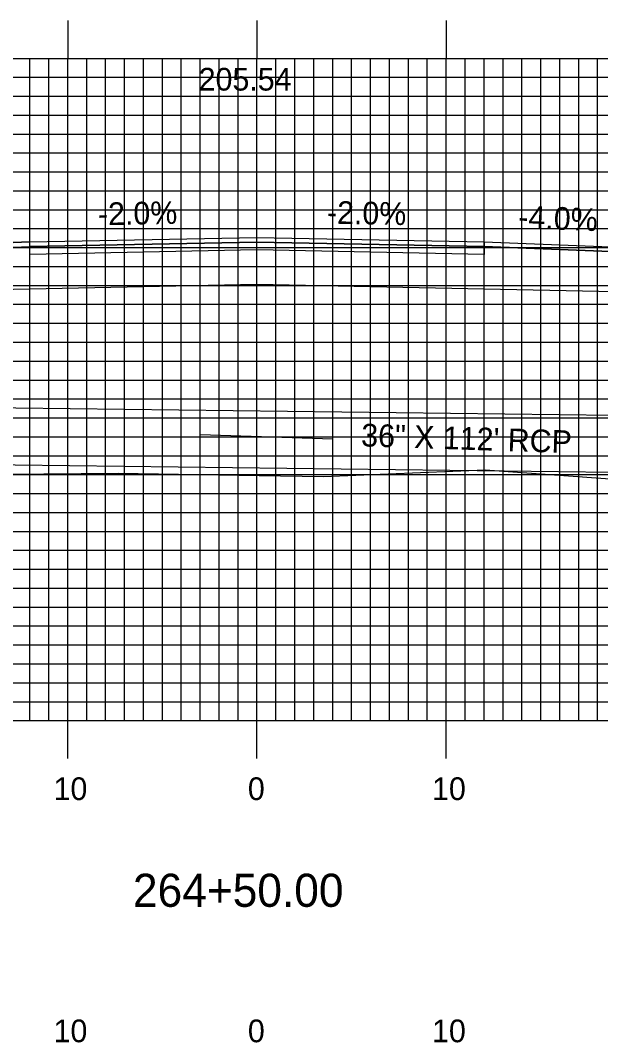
# Model space of a CAD drawing. Extents: x 1807045 to 1807388, y 442591 to 442811.
# Drawn here: x 1807198.3 to 1807228.9, y 442646.6 to 442700.7 of the extents above; entities that cross this region are included whole.
import ezdxf

# ---------------------------------------------------------------- set-up
doc = ezdxf.new("R2010")
doc.units = 0
for name, color, linetype in [('ANNOTATION', 7, 'Continuous'), ('D_Drainage_Culvert', 7, 'Continuous'), ('D_Drainage_Text', 7, 'Continuous'), ('D_Roadway_Centerline', 7, 'Continuous'), ('D_Roadway_Centerline_Text', 7, 'Continuous'), ('D_Roadway_Edge_Shoulder', 7, 'Continuous'), ('D_Roadway_Edge_TW', 7, 'Continuous'), ('D_Roadway_Pavement', 7, 'Continuous'), ('D_Roadway_SubGrade', 7, 'Continuous'), ('H_V ANNOTATION', 7, 'Continuous'), ('MAJOR', 7, 'Continuous'), ('MINOR', 7, 'Continuous'), ('S_Roadway_Centerline', 7, 'Continuous')]:
    doc.layers.add(name, color=color, linetype=linetype)

msp = doc.modelspace()

# ---------------------------------------------------------------- linework, layer by layer
at = {"layer": 'D_Drainage_Culvert'}
msp.add_line((1807207.759, 442678.786), (1807214.759, 442678.564), dxfattribs=at)
msp.add_lwpolyline([(1807157.759, 442677.672), (1807269.759, 442676.294), (1807269.796, 442679.294), (1807157.804, 442680.672)], close=True, dxfattribs=at)
at = {"layer": 'D_Roadway_Centerline'}
msp.add_lwpolyline([(1807166.273, 442681.484), (1807178.759, 442685.646), (1807180.585, 442686.103), (1807190.759, 442688.646), (1807198.759, 442688.966), (1807210.759, 442689.206), (1807222.759, 442688.966), (1807230.759, 442688.646), (1807240.933, 442686.103), (1807242.759, 442685.646), (1807258.793, 442680.302)], dxfattribs=at)
at = {"layer": 'D_Roadway_Edge_Shoulder'}
for points in [[(1807198.759, 442688.966), (1807190.759, 442688.646), (1807190.759, 442688.396), (1807198.759, 442688.716)], [(1807222.759, 442688.966), (1807230.759, 442688.646), (1807230.759, 442688.396), (1807222.759, 442688.716)]]:
    msp.add_lwpolyline(points, close=True, dxfattribs=at)
at = {"layer": 'D_Roadway_Edge_TW'}
msp.add_lwpolyline([(1807198.759, 442688.716), (1807198.759, 442688.966), (1807210.759, 442689.206), (1807222.759, 442688.966), (1807222.759, 442688.716), (1807210.759, 442688.956)], close=True, dxfattribs=at)
at = {"layer": 'D_Roadway_Pavement'}
msp.add_lwpolyline([(1807198.759, 442688.3), (1807198.759, 442688.716), (1807210.759, 442688.956), (1807222.759, 442688.716), (1807222.759, 442688.3), (1807210.759, 442688.54)], close=True, dxfattribs=at)
at = {"layer": 'D_Roadway_SubGrade'}
msp.add_lwpolyline([(1807198.759, 442686.466), (1807180.585, 442686.103), (1807190.759, 442688.646), (1807190.759, 442688.396), (1807198.759, 442688.716), (1807210.759, 442688.956), (1807222.759, 442688.716), (1807230.759, 442688.396), (1807230.759, 442688.646), (1807240.933, 442686.103), (1807222.759, 442686.466), (1807210.759, 442686.706)], close=True, dxfattribs=at)
at = {"layer": 'MAJOR'}
for p, q in [((1807200.759, 442700.669), (1807200.759, 442698.665)), ((1807210.759, 442700.669), (1807210.759, 442698.665)), ((1807220.759, 442700.669), (1807220.759, 442698.665)), ((1807070.759, 442698.665), (1807350.759, 442698.665)), ((1807070.759, 442698.665), (1807350.759, 442698.665)), ((1807200.759, 442663.665), (1807200.759, 442698.665)), ((1807210.759, 442663.665), (1807210.759, 442698.665)), ((1807220.759, 442663.665), (1807220.759, 442698.665)), ((1807070.759, 442693.665), (1807350.759, 442693.665)), ((1807070.759, 442688.665), (1807350.759, 442688.665)), ((1807070.759, 442683.665), (1807350.759, 442683.665)), ((1807070.759, 442678.665), (1807350.759, 442678.665)), ((1807070.759, 442673.665), (1807350.759, 442673.665)), ((1807070.759, 442668.665), (1807350.759, 442668.665)), ((1807070.759, 442663.665), (1807350.759, 442663.665)), ((1807070.759, 442663.665), (1807350.759, 442663.665)), ((1807200.759, 442661.661), (1807200.759, 442663.665)), ((1807210.759, 442661.661), (1807210.759, 442663.665)), ((1807220.759, 442661.661), (1807220.759, 442663.665))]:
    msp.add_line(p, q, dxfattribs=at)
at = {"layer": 'MINOR'}
for p, q in [((1807198.759, 442663.665), (1807198.759, 442698.665)), ((1807199.759, 442663.665), (1807199.759, 442698.665)), ((1807201.759, 442663.665), (1807201.759, 442698.665)), ((1807202.759, 442663.665), (1807202.759, 442698.665)), ((1807203.759, 442663.665), (1807203.759, 442698.665)), ((1807204.759, 442663.665), (1807204.759, 442698.665)), ((1807205.759, 442663.665), (1807205.759, 442698.665)), ((1807206.759, 442663.665), (1807206.759, 442698.665)), ((1807207.759, 442663.665), (1807207.759, 442698.665)), ((1807208.759, 442663.665), (1807208.759, 442698.665)), ((1807209.759, 442663.665), (1807209.759, 442698.665)), ((1807211.759, 442663.665), (1807211.759, 442698.665)), ((1807212.759, 442663.665), (1807212.759, 442698.665)), ((1807213.759, 442663.665), (1807213.759, 442698.665)), ((1807214.759, 442663.665), (1807214.759, 442698.665)), ((1807215.759, 442663.665), (1807215.759, 442698.665)), ((1807216.759, 442663.665), (1807216.759, 442698.665)), ((1807217.759, 442663.665), (1807217.759, 442698.665)), ((1807218.759, 442663.665), (1807218.759, 442698.665)), ((1807219.759, 442663.665), (1807219.759, 442698.665)), ((1807221.759, 442663.665), (1807221.759, 442698.665)), ((1807222.759, 442663.665), (1807222.759, 442698.665)), ((1807223.759, 442663.665), (1807223.759, 442698.665)), ((1807224.759, 442663.665), (1807224.759, 442698.665)), ((1807225.759, 442663.665), (1807225.759, 442698.665)), ((1807226.759, 442663.665), (1807226.759, 442698.665)), ((1807227.759, 442663.665), (1807227.759, 442698.665)), ((1807228.759, 442663.665), (1807228.759, 442698.665)), ((1807070.759, 442697.665), (1807350.759, 442697.665)), ((1807070.759, 442696.665), (1807350.759, 442696.665)), ((1807070.759, 442695.665), (1807350.759, 442695.665)), ((1807070.759, 442694.665), (1807350.759, 442694.665)), ((1807070.759, 442692.665), (1807350.759, 442692.665)), ((1807070.759, 442691.665), (1807350.759, 442691.665)), ((1807070.759, 442690.665), (1807350.759, 442690.665)), ((1807070.759, 442689.665), (1807350.759, 442689.665)), ((1807070.759, 442687.665), (1807350.759, 442687.665)), ((1807070.759, 442686.665), (1807350.759, 442686.665)), ((1807070.759, 442685.665), (1807350.759, 442685.665)), ((1807070.759, 442684.665), (1807350.759, 442684.665)), ((1807070.759, 442682.665), (1807350.759, 442682.665)), ((1807070.759, 442681.665), (1807350.759, 442681.665)), ((1807070.759, 442680.665), (1807350.759, 442680.665)), ((1807070.759, 442679.665), (1807350.759, 442679.665)), ((1807070.759, 442677.665), (1807350.759, 442677.665)), ((1807070.759, 442676.665), (1807350.759, 442676.665)), ((1807070.759, 442675.665), (1807350.759, 442675.665)), ((1807070.759, 442674.665), (1807350.759, 442674.665)), ((1807070.759, 442672.665), (1807350.759, 442672.665)), ((1807070.759, 442671.665), (1807350.759, 442671.665)), ((1807070.759, 442670.665), (1807350.759, 442670.665)), ((1807070.759, 442669.665), (1807350.759, 442669.665)), ((1807070.759, 442667.665), (1807350.759, 442667.665)), ((1807070.759, 442666.665), (1807350.759, 442666.665)), ((1807070.759, 442665.665), (1807350.759, 442665.665)), ((1807070.759, 442664.665), (1807350.759, 442664.665))]:
    msp.add_line(p, q, dxfattribs=at)
at = {"layer": 'S_Roadway_Centerline'}
msp.add_lwpolyline([(1807137.321, 442678.055), (1807145.714, 442677.905), (1807153.421, 442677.695), (1807163.888, 442677.64), (1807167.09, 442677.522), (1807176.514, 442677.036), (1807189.139, 442676.626), (1807189.4, 442676.62), (1807189.676, 442676.614), (1807203.419, 442676.739), (1807210.876, 442676.624), (1807214.273, 442676.566), (1807222.824, 442676.92), (1807231.138, 442676.312), (1807247.162, 442676.483), (1807251.677, 442676.55), (1807259.938, 442676.383), (1807289.258, 442676.117)], dxfattribs=at)

# ---------------------------------------------------------------- texts
at = {"layer": 'ANNOTATION'}
for s, rotation, p in [('-2.0%', 1.1458, (1807202.365, 442689.839)), ('-2.0%', 358.8542, (1807214.445, 442689.933)), ('-4.0%', 357.7094, (1807224.55, 442689.696))]:
    msp.add_text(s, height=1.2, rotation=rotation, dxfattribs=at).set_placement(p)
at = {"layer": 'D_Drainage_Text'}
msp.add_text('36" X 112\' RCP', height=1.2, rotation=358.1149, dxfattribs=at).set_placement((1807216.249, 442678.162))
at = {"layer": 'D_Roadway_Centerline'}
for s, p in [('C', (1807210.754, 442689.206)), ('L', (1807210.759, 442689.199))]:
    msp.add_text(s, height=0.0146, dxfattribs=at).set_placement(p)
at = {"layer": 'D_Roadway_Centerline_Text'}
msp.add_text('205.54', height=1.2, dxfattribs=at).set_placement((1807207.676, 442696.963))
at = {"layer": 'H_V ANNOTATION'}
for s, height, p in [('10', 1.2, (1807200.009, 442659.465)), ('0', 1.2, (1807210.277, 442659.465)), ('10', 1.2, (1807220.009, 442659.465)), ('264+50.00', 1.75, (1807204.204, 442653.821)), ('10', 1.2, (1807200.009, 442646.665)), ('0', 1.2, (1807210.277, 442646.665)), ('10', 1.2, (1807220.009, 442646.665))]:
    msp.add_text(s, height=height, dxfattribs=at).set_placement(p)

doc.saveas('drawing.dxf')
